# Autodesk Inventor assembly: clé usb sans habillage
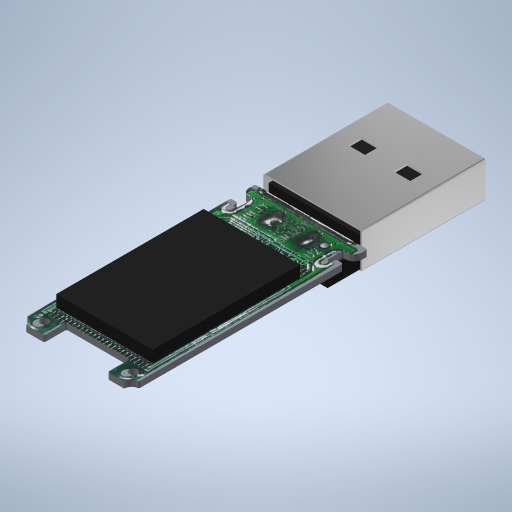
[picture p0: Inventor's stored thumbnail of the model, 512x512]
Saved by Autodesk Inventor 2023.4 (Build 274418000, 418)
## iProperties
Created: 2013-04
Part Number: clé usb sans habillage
Document SubType Name: Assembly
Designer: hilarion
Author: hilarion
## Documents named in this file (4)
- D:\travail\année 2025-2026\ITEC\it\clé usb sans habillage.iam
- C:\Users\mel\Downloads\clé usb (1)\usb gris.ipt
- C:\Users\mel\Downloads\clé usb (1)\usb noir.ipt
- C:\Users\mel\Downloads\clé usb (1)\carte.ipt
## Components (3 placed, 3 different names)
1. usb gris:1 — Affleurement:1, Placage:1, Placage:2
2. usb noir:1 — Affleurement:1, Placage:1, Placage:2, Affleurement:2
3. carte:1 — Affleurement:2
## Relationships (4: Flush 2, Mate 2)
- Affleurement:1 [Flush]: usb gris:1 ↔ usb noir:1
- Placage:1 [Mate]: usb gris:1 ↔ usb noir:1
- Placage:2 [Mate]: usb gris:1 ↔ usb noir:1
- Affleurement:2 [Flush]: usb noir:1 ↔ carte:1
